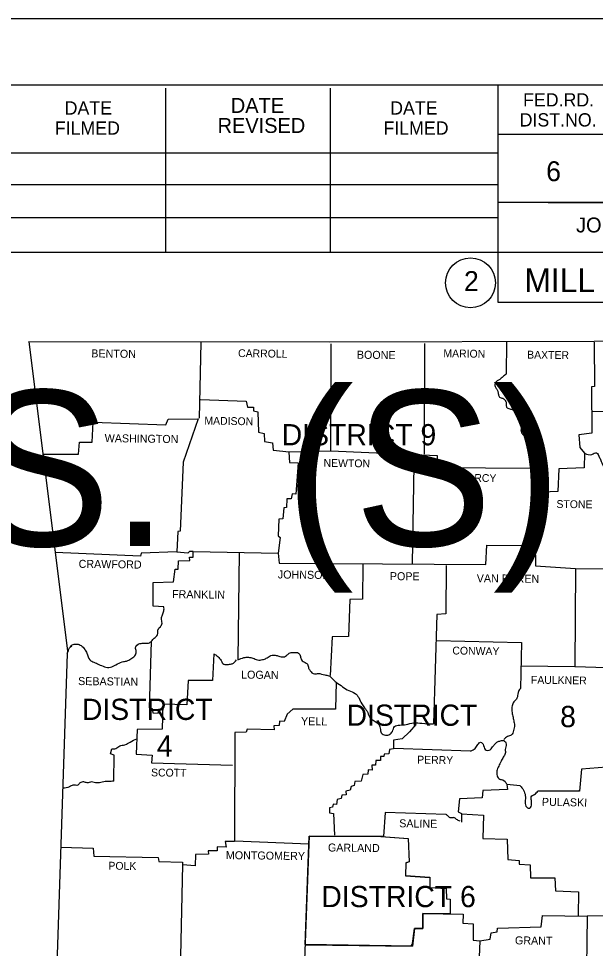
# Model space of a CAD drawing. Extents: x 1367863 to 1368197, y 380048 to 380261.
# Drawn here: x 1368120.7 to 1368154.6, y 380206.7 to 380261.4 of the extents above; entities that cross this region are included whole.
import ezdxf

# ---------------------------------------------------------------- set-up
doc = ezdxf.new("R2010")
doc.units = 0
for name, color, linetype in [('R_Border', 7, 'Continuous'), ('R_Dimension', 7, 'Continuous'), ('R_Draft', 7, 'Continuous'), ('R_No Plot', 7, 'Continuous')]:
    doc.layers.add(name, color=color, linetype=linetype)

msp = doc.modelspace()

# ---------------------------------------------------------------- linework, layer by layer
at = {"layer": 'R_Border'}
for p, q in [((1367875.8, 380257.536), (1368191.969, 380257.536)), ((1368129.331, 380247.657), (1368129.331, 380257.336)), ((1368139.011, 380247.657), (1368139.011, 380257.336)), ((1368148.87, 380257.536), (1368148.87, 380244.737)), ((1368191.969, 380254.596), (1368148.87, 380254.596)), ((1368109.712, 380253.516), (1368148.87, 380253.516)), ((1368109.712, 380251.656), (1368148.87, 380251.656)), ((1368191.969, 380250.596), (1368148.87, 380250.596)), ((1368151.83, 380250.596), (1368191.969, 380250.596)), ((1368109.712, 380249.717), (1368148.87, 380249.717)), ((1368191.969, 380247.657), (1368109.712, 380247.657)), ((1368148.87, 380244.737), (1368191.969, 380244.737)), ((1368122.81, 380229.99), (1368122.816, 380229.995)), ((1368130.054, 380229.008), (1368130.058, 380229.011)), ((1368123.719, 380224.433), (1368123.786, 380224.5)), ((1368127.567, 380224.463), (1368127.697, 380224.593))]:
    msp.add_line(p, q, dxfattribs=at)
for points in [[(1368121.261, 380242.407), (1368138.984, 380242.397), (1368154.536, 380242.437), (1368172.886, 380242.716), (1368181.384, 380242.915)], [(1368163.821, 380242.527), (1368163.841, 380239.817), (1368162.416, 380239.737), (1368162.376, 380238.243), (1368154.446, 380238.293)], [(1368121.261, 380242.407), (1368122.809, 380229.996)], [(1368131.383, 380242.347), (1368131.283, 380237.904)], [(1368131.363, 380238.99), (1368134.053, 380238.9), (1368134.123, 380238.552), (1368134.491, 380238.542), (1368134.481, 380238.322), (1368134.75, 380238.263), (1368134.77, 380237.067), (1368135.109, 380236.988), (1368135.129, 380236.519), (1368135.607, 380236.45), (1368135.637, 380236.011), (1368136.583, 380235.912), (1368139.044, 380235.971), (1368139.064, 380242.268)], [(1368144.553, 380242.288), (1368144.523, 380235.782)], [(1368149.375, 380242.367), (1368149.355, 380240.494)], [(1368154.536, 380242.367), (1368154.556, 380239.757), (1368154.376, 380239.747), (1368154.406, 380237.017), (1368153.639, 380236.908), (1368153.699, 380236.171), (1368153.968, 380235.832), (1368153.948, 380234.975), (1368152.453, 380234.915), (1368152.404, 380233.58), (1368151.039, 380233.531), (1368150.979, 380231.917), (1368151.049, 380231.777), (1368151.089, 380229.197), (1368153.43, 380229.037), (1368153.4, 380223.269), (1368155.263, 380223.209), (1368155.263, 380217.342), (1368153.788, 380217.232), (1368153.679, 380215.937), (1368151.218, 380215.927)], [(1368122.128, 380235.782), (1368124.18, 380235.772), (1368124.24, 380236.489), (1368124.987, 380236.489), (1368125.057, 380237.665), (1368129.331, 380237.516), (1368129.46, 380237.844), (1368131.224, 380237.854), (1368130.337, 380235.314), (1368130.167, 380231.249), (1368130.028, 380231.229), (1368129.97, 380230.035)], [(1368136.563, 380235.892), (1368136.603, 380235.294), (1368137.111, 380235.264), (1368136.982, 380233.421), (1368136.753, 380233.441), (1368136.703, 380233.142), (1368136.444, 380233.142), (1368136.434, 380232.634), (1368136.265, 380232.624), (1368136.215, 380231.976), (1368135.976, 380231.947), (1368135.936, 380230.96), (1368136.045, 380230.881), (1368135.936, 380229.954)], [(1368139.044, 380235.971), (1368145.29, 380235.702), (1368145.281, 380234.995), (1368151.009, 380234.945)], [(1368151.039, 380233.531), (1368151.029, 380236.001)], [(1368143.786, 380235.732), (1368143.776, 380235.164), (1368143.916, 380235.134), (1368143.826, 380229.346)], [(1368135.996, 380229.366), (1368148.16, 380229.277), (1368148.209, 380230.422), (1368151.039, 380230.392)], [(1368129.97, 380230.035), (1368127.866, 380229.944), (1368127.836, 380229.765), (1368122.809, 380229.996)], [(1368122.809, 380229.996), (1368123.533, 380224.196), (1368123.527, 380224.038)], [(1368129.211, 380226.786), (1368128.573, 380226.826), (1368128.583, 380228.221), (1368129.769, 380228.27), (1368129.869, 380229.008), (1368130.058, 380229.008), (1368130.068, 380229.506), (1368130.735, 380229.516), (1368130.725, 380229.715), (1368130.935, 380229.715), (1368130.934, 380230.049)], [(1368130.934, 380230.049), (1368130.715, 380230.054), (1368130.616, 380229.954), (1368129.968, 380230.004), (1368129.97, 380230.035)], [(1368130.942, 380230.049), (1368135.936, 380229.954), (1368135.996, 380229.366)], [(1368133.634, 380229.994), (1368133.565, 380223.668)], [(1368140.917, 380229.287), (1368140.907, 380227.234), (1368140.15, 380227.224), (1368140.08, 380225.043), (1368139.114, 380225.013), (1368139.004, 380222.751)], [(1368145.828, 380229.227), (1368145.799, 380226.378), (1368145.281, 380226.338), (1368145.071, 380219.892)], [(1368153.43, 380229.037), (1368159.059, 380229.008), (1368159.547, 380229.237), (1368159.517, 380224.953), (1368159.178, 380224.813), (1368158.889, 380224.554), (1368158.79, 380224.465), (1368158.78, 380223.229), (1368155.193, 380223.229)], [(1368128.468, 380224.755), (1368128.354, 380220.848), (1368128.524, 380220.799), (1368128.554, 380220.54), (1368128.882, 380220.52), (1368128.912, 380220.699), (1368129.181, 380220.749)], [(1368145.251, 380224.813), (1368150.262, 380224.694), (1368150.192, 380221.984)], [(1368123.527, 380224.038), (1368122.546, 380194.468)], [(1368132.15, 380224.026), (1368132.07, 380222.452), (1368130.646, 380222.442), (1368130.566, 380221.018), (1368129.151, 380221.048), (1368129.111, 380219.583), (1368127.637, 380219.573), (1368127.587, 380218.109), (1368128.524, 380218.049), (1368128.484, 380217.601), (1368133.246, 380217.471)], [(1368150.212, 380223.309), (1368153.4, 380223.269)], [(1368139.353, 380222.343), (1368139.303, 380220.769), (1368136.802, 380220.759), (1368136.474, 380220.47), (1368136.294, 380220.031), (1368136.015, 380220.051), (1368136.005, 380219.802), (1368135.687, 380219.772), (1368135.697, 380219.543), (1368134.113, 380219.583), (1368134.053, 380219.414), (1368133.395, 380219.384), (1368133.375, 380212.978), (1368132.827, 380212.968), (1368132.867, 380212.639), (1368132.349, 380212.649), (1368132.339, 380212.41), (1368131.821, 380212.41), (1368131.831, 380212.231), (1368131.064, 380212.211), (1368131.054, 380211.543), (1368130.307, 380211.603), (1368130.187, 380206.214)], [(1368144.045, 380219.852), (1368143.657, 380219.424), (1368143.228, 380219.015), (1368142.73, 380218.936), (1368142.73, 380218.418), (1368142.491, 380218.388), (1368142.451, 380218.129), (1368142.172, 380218.109), (1368142.152, 380217.979), (1368141.963, 380217.969), (1368141.953, 380217.74), (1368141.694, 380217.73), (1368141.674, 380217.471), (1368141.455, 380217.471), (1368141.465, 380217.162), (1368141.226, 380217.182), (1368141.206, 380216.943), (1368140.917, 380216.923), (1368140.827, 380216.525), (1368140.459, 380216.495), (1368140.419, 380216.276), (1368140.23, 380216.216), (1368140.17, 380215.987), (1368139.921, 380215.937), (1368139.941, 380215.708), (1368139.692, 380215.688), (1368139.642, 380215.508), (1368139.413, 380215.439), (1368139.363, 380215.15), (1368139.183, 380215.16), (1368139.134, 380215), (1368138.964, 380214.951), (1368138.954, 380214.652), (1368139.203, 380214.612), (1368139.253, 380213.337)], [(1368126.262, 380216.515), (1368126.292, 380218.059), (1368126.073, 380218.129), (1368126.143, 380218.418)], [(1368147.263, 380218.288), (1368142.74, 380218.437)], [(1368150.182, 380216.246), (1368149.395, 380216.325), (1368149.435, 380216.036), (1368147.99, 380215.977), (1368147.95, 380215.548), (1368146.606, 380215.479), (1368146.526, 380214.711), (1368146.725, 380214.612), (1368146.725, 380214.104)], [(1368153.629, 380215.947), (1368153.679, 380215.997)], [(1368145.828, 380214.562), (1368142.242, 380214.672), (1368142.142, 380213.257), (1368137.759, 380213.287), (1368137.739, 380212.809)], [(1368146.725, 380214.607), (1368148.03, 380214.522), (1368147.98, 380213.147), (1368149.415, 380213.098), (1368149.445, 380211.902), (1368150.122, 380211.842), (1368150.122, 380211.643), (1368150.76, 380211.593), (1368150.78, 380210.826), (1368152.224, 380210.826), (1368152.264, 380210.069), (1368153.609, 380210.009), (1368153.599, 380208.585)], [(1368137.74, 380212.813), (1368133.377, 380212.982)], [(1368137.52, 380206.901), (1368137.759, 380213.287), (1368142.142, 380213.267)], [(1368137.759, 380213.227), (1368137.819, 380213.287)], [(1368141.973, 380213.267), (1368143.597, 380213.147), (1368143.647, 380211.763), (1368143.457, 380211.703), (1368143.437, 380210.966), (1368144.872, 380210.866), (1368144.872, 380210.258), (1368145.828, 380210.208), (1368145.838, 380209.601), (1368146.068, 380209.571), (1368146.058, 380208.704)], [(1368142.272, 380213.237), (1368143.597, 380213.137), (1368143.647, 380211.763), (1368143.457, 380211.693), (1368143.437, 380210.956), (1368144.872, 380210.856), (1368144.872, 380210.258), (1368145.828, 380210.199), (1368145.838, 380209.601), (1368146.068, 380209.571), (1368146.058, 380208.754)], [(1368123.154, 380212.639), (1368125.047, 380212.57), (1368125.087, 380212.111), (1368128.882, 380212.032), (1368128.922, 380211.792), (1368130.307, 380211.753), (1368130.297, 380211.543)], [(1368137.739, 380212.809), (1368137.48, 380205.984)], [(1368166.67, 380209.84), (1368162.525, 380209.949), (1368162.506, 380208.604), (1368154.117, 380208.575)], [(1368146.058, 380208.704), (1368144.454, 380208.724), (1368144.444, 380207.847), (1368143.956, 380207.847), (1368143.836, 380206.811), (1368137.52, 380206.901)], [(1368137.56, 380206.891), (1368143.826, 380206.801), (1368143.956, 380207.847), (1368144.444, 380207.847), (1368144.454, 380208.724), (1368146.825, 380208.694), (1368146.805, 380208.166), (1368147.412, 380208.116), (1368147.412, 380207.16), (1368147.811, 380207.12)], [(1368147.811, 380207.12), (1368148.419, 380207.21), (1368148.468, 380207.588), (1368148.827, 380207.648), (1368148.847, 380207.867), (1368151.407, 380207.947), (1368151.497, 380208.614), (1368154.117, 380208.575)], [(1368154.117, 380208.545), (1368154.057, 380204.121), (1368153.798, 380204.111), (1368153.769, 380201.362)], [(1368143.746, 380206.811), (1368143.846, 380206.921)], [(1368147.811, 380207.12), (1368147.681, 380204.251), (1368147.582, 380204.281), (1368147.592, 380202.796)]]:
    msp.add_lwpolyline(points, dxfattribs=at)
msp.add_circle((1368147.257, 380245.872), 1.467, dxfattribs=at)
for points in [[(1368149.355, 380240.494), (1368149.156, 380240.325), (1368148.977, 380240.175), (1368148.718, 380239.986), (1368148.688, 380239.817), (1368148.777, 380239.638), (1368148.857, 380239.498), (1368148.897, 380239.299), (1368148.967, 380239.139), (1368149.156, 380239.07), (1368149.305, 380238.93), (1368149.365, 380238.731), (1368149.385, 380238.542), (1368149.564, 380238.452), (1368149.754, 380238.392), (1368149.943, 380238.263), (1368150.033, 380238.093), (1368150.053, 380237.884), (1368150.132, 380237.725), (1368150.222, 380237.525), (1368150.242, 380237.356), (1368150.222, 380237.197), (1368150.262, 380237.037), (1368150.401, 380236.888), (1368150.66, 380236.808), (1368150.83, 380236.699), (1368150.949, 380236.549), (1368150.879, 380236.36), (1368150.889, 380236.2), (1368150.989, 380236.001)], [(1368153.968, 380235.832), (1368154.406, 380235.762), (1368154.665, 380235.862), (1368154.854, 380235.573), (1368154.954, 380235.354), (1368155.113, 380235.035), (1368155.382, 380234.935), (1368155.582, 380234.766), (1368155.582, 380234.577), (1368155.402, 380234.397), (1368155.273, 380234.228), (1368155.313, 380234.019), (1368155.362, 380233.73), (1368155.362, 380233.461), (1368155.293, 380233.202), (1368155.233, 380232.973), (1368155.293, 380232.783), (1368155.502, 380232.813), (1368155.721, 380232.973), (1368155.95, 380232.973), (1368156.169, 380232.853), (1368156.399, 380232.644), (1368156.628, 380232.694), (1368156.817, 380232.743), (1368157.076, 380232.823), (1368157.265, 380232.724), (1368157.425, 380232.594), (1368157.624, 380232.385), (1368157.813, 380232.255), (1368158.052, 380232.136), (1368158.351, 380232.056), (1368158.62, 380231.867), (1368158.67, 380231.548), (1368158.66, 380231.279), (1368158.64, 380230.94), (1368158.61, 380230.562), (1368158.65, 380230.203), (1368158.77, 380229.964), (1368158.919, 380229.675), (1368158.959, 380229.416), (1368158.949, 380228.998)], [(1368123.527, 380224.038), (1368123.881, 380224.574), (1368124.09, 380224.594), (1368124.349, 380224.505), (1368124.549, 380224.285), (1368124.678, 380224.066), (1368124.858, 380223.658), (1368125.087, 380223.528), (1368125.386, 380223.399), (1368125.714, 380223.259), (1368126.063, 380223.229), (1368126.392, 380223.379), (1368126.76, 380223.548), (1368127.019, 380223.598), (1368127.268, 380223.718), (1368127.498, 380223.897), (1368127.587, 380224.146), (1368127.547, 380224.395), (1368127.637, 380224.554), (1368127.866, 380224.634), (1368128.095, 380224.644), (1368128.364, 380224.674), (1368128.524, 380224.813), (1368128.693, 380224.983), (1368128.862, 380225.212), (1368128.862, 380225.431), (1368129.002, 380225.61), (1368129.101, 380225.83), (1368129.072, 380226.109), (1368129.121, 380226.308), (1368129.211, 380226.557), (1368129.211, 380226.786)], [(1368132.15, 380224.026), (1368132.389, 380223.867), (1368132.578, 380223.618), (1368132.738, 380223.409), (1368133.017, 380223.399), (1368133.236, 380223.439), (1368133.485, 380223.658)], [(1368133.565, 380223.668), (1368133.923, 380223.797), (1368134.182, 380223.817), (1368134.451, 380223.767), (1368134.72, 380223.658), (1368135.019, 380223.678), (1368135.238, 380223.757), (1368135.458, 380223.897), (1368135.697, 380223.947), (1368135.926, 380223.897), (1368136.165, 380223.837), (1368136.434, 380223.917), (1368136.583, 380224.056), (1368136.852, 380224.096), (1368137.081, 380224.096), (1368137.241, 380223.917), (1368137.281, 380223.718), (1368137.48, 380223.528), (1368137.669, 380223.409), (1368137.729, 380223.18), (1368137.829, 380223.01), (1368137.918, 380222.901), (1368138.068, 380222.841), (1368138.307, 380222.861), (1368138.675, 380222.781), (1368138.924, 380222.731), (1368139.144, 380222.542), (1368139.353, 380222.343)], [(1368139.353, 380222.343), (1368139.731, 380222.084), (1368140.09, 380221.855), (1368140.469, 380221.685), (1368140.678, 380221.446), (1368140.857, 380221.077), (1368141.017, 380220.848), (1368141.206, 380220.559), (1368141.355, 380220.241), (1368141.584, 380220.071), (1368141.824, 380219.912), (1368141.943, 380219.643), (1368142.003, 380219.364), (1368142.262, 380219.234), (1368142.511, 380219.284), (1368142.66, 380219.454), (1368142.79, 380219.733), (1368143.089, 380219.822), (1368143.467, 380219.862), (1368143.906, 380219.952), (1368144.394, 380219.932), (1368145.071, 380219.892)], [(1368150.192, 380221.984), (1368150.053, 380221.735), (1368149.993, 380221.406), (1368149.813, 380221.197), (1368149.704, 380220.958), (1368149.694, 380220.639), (1368149.744, 380220.35), (1368149.803, 380220.081), (1368149.843, 380219.822), (1368149.793, 380219.503), (1368149.654, 380219.234), (1368149.435, 380219.155), (1368149.226, 380218.975)], [(1368126.143, 380218.418), (1368126.382, 380218.447), (1368126.611, 380218.597), (1368126.92, 380218.667), (1368127.229, 380218.826), (1368127.627, 380219.015)], [(1368147.263, 380218.288), (1368147.532, 380218.447), (1368147.681, 380218.677), (1368147.851, 380218.816), (1368148.03, 380218.617), (1368148.18, 380218.338), (1368148.349, 380218.338), (1368148.558, 380218.537), (1368148.688, 380218.706), (1368148.847, 380218.836), (1368149.026, 380218.896), (1368149.216, 380218.916), (1368149.355, 380218.706), (1368149.305, 380218.378), (1368149.305, 380218.158), (1368149.186, 380217.929), (1368149.056, 380217.69), (1368148.917, 380217.411), (1368148.807, 380217.122), (1368148.827, 380216.833), (1368148.977, 380216.644), (1368149.156, 380216.594), (1368149.395, 380216.355)], [(1368126.262, 380216.515), (1368125.943, 380216.505), (1368125.585, 380216.465), (1368125.256, 380216.415), (1368124.957, 380216.475), (1368124.688, 380216.425), (1368124.499, 380216.475), (1368124.27, 380216.415), (1368124.14, 380216.286), (1368123.861, 380216.286), (1368123.662, 380216.196), (1368123.254, 380216.104)], [(1368150.182, 380216.246), (1368150.371, 380215.997), (1368150.481, 380215.668), (1368150.481, 380215.299), (1368150.571, 380214.99), (1368150.75, 380214.931), (1368150.85, 380215.19), (1368150.83, 380215.449), (1368150.83, 380215.608), (1368151.019, 380215.738), (1368151.218, 380215.927)], [(1368146.645, 380214.164), (1368146.436, 380214.273), (1368146.277, 380214.373), (1368146.097, 380214.353), (1368145.958, 380214.443), (1368145.828, 380214.562)]]:
    msp.add_spline(points, degree=3, dxfattribs=at)
at = {"layer": 'R_Draft'}
msp.add_line((1368145.28, 380226.314), (1368145.306, 380226.34), dxfattribs=at)
at = {"layer": 'R_No Plot'}
for p in [(1367863.388, 380261.431), (1367863.4, 380261.431)]:
    msp.add_line(p, (1368196.721, 380261.431), dxfattribs=at)
msp.add_lwpolyline([(1367863.393, 380261.431), (1368196.721, 380261.431), (1368196.721, 380048.101), (1367863.393, 380048.101)], close=True, dxfattribs=at)

# ---------------------------------------------------------------- texts
at = {"layer": 'R_Border'}
for s, height, rotation, p in [('DATE', 0.8792, 360, (1368133.151, 380255.876)), ('FED.RD.', 0.7819, 360, (1368150.35, 380256.256)), ('DATE', 0.7819, 360, (1368123.371, 380255.776)), ('DATE', 0.7819, 360, (1368142.531, 380255.776)), ('DIST.NO.', 0.7819, 360, (1368150.15, 380255.076)), ('FILMED', 0.7819, 360, (1368122.791, 380254.596)), ('REVISED', 0.8792, 360, (1368132.371, 380254.696)), ('FILMED', 0.7819, 360, (1368142.131, 380254.596)), ('6', 1.172, 360, (1368151.71, 380251.856)), ('JOB NO.', 0.8792, 360, (1368153.47, 380248.837)), ('2', 1.172, 360, (1368146.874, 380245.386)), ('MILL CREEK STR. & APPRS. (S)', 1.39995, 360, (1368150.427, 380245.32)), ('BENTON', 0.4713, 359.2527, (1368124.937, 380241.481)), ('CARROLL', 0.4603, 359.1481, (1368133.575, 380241.5)), ('MARION', 0.4603, 359.1854, (1368145.659, 380241.491)), ('BOONE', 0.4713, 359.4001, (1368140.568, 380241.401)), ('BAXTER', 0.4603, 359.2559, (1368150.59, 380241.411)), ('MADISON', 0.4603, 359.0906, (1368131.592, 380237.525)), ('WASHINGTON', 0.4711, 359.232, (1368125.724, 380236.489)), ('NEWTON', 0.4603, 359.2717, (1368138.606, 380235.035)), ('SEARCY', 0.4601, 359.2527, (1368146.247, 380234.168)), ('STONE', 0.4601, 359.4001, (1368152.314, 380232.614)), ('CRAWFORD', 0.4711, 359.2771, (1368124.19, 380229.087)), ('JOHNSON', 0.4713, 359.3514, (1368135.916, 380228.46)), ('POPE', 0.4713, 359.6155, (1368142.511, 380228.36)), ('VAN BUREN', 0.4713, 359.3508, (1368147.622, 380228.24)), ('FRANKLIN', 0.4713, 359.1815, (1368129.689, 380227.304)), ('CONWAY', 0.4601, 359.0371, (1368146.187, 380223.987)), ('LOGAN', 0.4713, 359.3969, (1368133.754, 380222.562)), ('SEBASTIAN', 0.4711, 359.2816, (1368124.16, 380222.183)), ('FAULKNER', 0.4603, 359.2486, (1368150.81, 380222.263)), ('YELL', 0.4713, 359.1987, (1368137.281, 380219.822)), ('PERRY', 0.4603, 359.0858, (1368144.115, 380217.561)), ('SCOTT', 0.4603, 359.4063, (1368128.454, 380216.804)), ('PULASKI', 0.4713, 359.053, (1368151.457, 380215.07)), ('SALINE', 0.4713, 359.1491, (1368143.059, 380213.805)), ('MONTGOMERY', 0.4713, 359.2944, (1368132.857, 380211.932)), ('GARLAND', 0.4713, 359.3658, (1368138.865, 380212.38)), ('POLK', 0.4601, 359.2152, (1368125.943, 380211.314)), ('GRANT', 0.4713, 359.4032, (1368149.873, 380206.911))]:
    msp.add_text(s, height=height, rotation=rotation, dxfattribs=at).set_placement(p)
for s, height, p in [('DISTRICT 9', 1.2493, (1368136.145, 380236.3)), ('DISTRICT', 1.2493, (1368124.384, 380220.127)), ('DISTRICT', 1.2493, (1368139.961, 380219.782)), ('8', 1.249, (1368152.533, 380219.703)), ('4', 1.249, (1368128.793, 380217.969)), ('DISTRICT 6', 1.2493, (1368138.474, 380209.102))]:
    msp.add_text(s, height=height, dxfattribs=at).set_placement(p)
at = {"layer": 'R_Dimension'}
msp.add_text('MILL CREEK STR.  & APPRS.  (S)', height=9.16, dxfattribs=at).set_placement((1367962.058, 380230.375))

doc.saveas('drawing.dxf')
